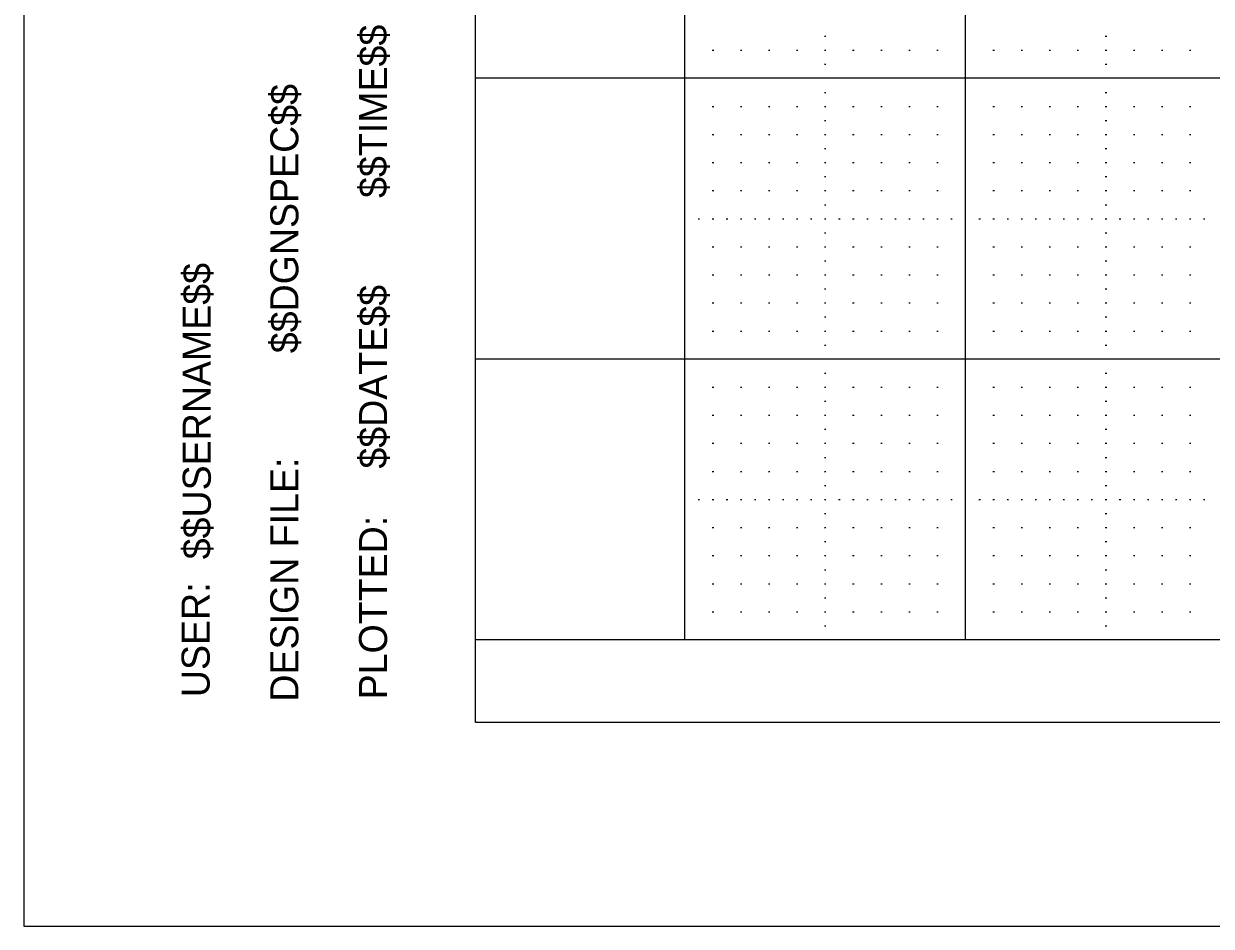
# Model space of a CAD drawing. Extents: x -1.3 to 32.7, y -0.7 to 21.3.
# Drawn here: x -1.263 to 2.967, y -0.727 to 2.487 of the extents above; entities that cross this region are included whole.
import ezdxf

# ---------------------------------------------------------------- set-up
doc = ezdxf.new("R2010")
doc.units = 0
for name, color, linetype in [('Level 1', 7, 'Continuous'), ('Level 4', 7, 'Continuous'), ('Level 5', 7, 'Continuous'), ('Level 63', 7, 'Continuous'), ('R_Border_Dark', 7, 'Continuous')]:
    doc.layers.add(name, color=color, linetype=linetype)

msp = doc.modelspace()

# ---------------------------------------------------------------- linework, layer by layer
at = {"layer": 'Level 1'}
for p, q in [((-1.263, 21.273), (-1.263, -0.727)), ((0.3463, -0.001), (0.3463, 20.545)), ((31.9643, -0.001), (0.3463, -0.001))]:
    msp.add_line(p, q, dxfattribs=at)
at = {"layer": 'Level 4'}
msp.add_line((31.9643, 0.293), (0.3463, 0.293), dxfattribs=at)
at = {"layer": 'Level 5'}
for p, q in [((1.5898, 2.443), (1.5948, 2.443)), ((2.5898, 2.443), (2.5948, 2.443)), ((1.1898, 2.393), (1.1948, 2.393)), ((1.2898, 2.393), (1.2948, 2.393)), ((1.3898, 2.393), (1.3948, 2.393)), ((1.4898, 2.393), (1.4948, 2.393)), ((1.5898, 2.393), (1.5948, 2.393)), ((1.6898, 2.393), (1.6948, 2.393)), ((1.7898, 2.393), (1.7948, 2.393)), ((1.8898, 2.393), (1.8948, 2.393)), ((1.9898, 2.393), (1.9948, 2.393)), ((2.1898, 2.393), (2.1948, 2.393)), ((2.2898, 2.393), (2.2948, 2.393)), ((2.3898, 2.393), (2.3948, 2.393)), ((2.4898, 2.393), (2.4948, 2.393)), ((2.5898, 2.393), (2.5948, 2.393)), ((2.6898, 2.393), (2.6948, 2.393)), ((2.7898, 2.393), (2.7948, 2.393)), ((2.8898, 2.393), (2.8948, 2.393)), ((1.5898, 2.343), (1.5948, 2.343)), ((2.5898, 2.343), (2.5948, 2.343)), ((1.5898, 2.243), (1.5948, 2.243)), ((2.5898, 2.243), (2.5948, 2.243)), ((1.1898, 2.193), (1.1948, 2.193)), ((1.2898, 2.193), (1.2948, 2.193)), ((1.3898, 2.193), (1.3948, 2.193)), ((1.4898, 2.193), (1.4948, 2.193)), ((1.5898, 2.193), (1.5948, 2.193)), ((1.6898, 2.193), (1.6948, 2.193)), ((1.7898, 2.193), (1.7948, 2.193)), ((1.8898, 2.193), (1.8948, 2.193)), ((1.9898, 2.193), (1.9948, 2.193)), ((2.1898, 2.193), (2.1948, 2.193)), ((2.2898, 2.193), (2.2948, 2.193)), ((2.3898, 2.193), (2.3948, 2.193)), ((2.4898, 2.193), (2.4948, 2.193)), ((2.5898, 2.193), (2.5948, 2.193)), ((2.6898, 2.193), (2.6948, 2.193)), ((2.7898, 2.193), (2.7948, 2.193)), ((2.8898, 2.193), (2.8948, 2.193)), ((1.5898, 2.143), (1.5948, 2.143)), ((2.5898, 2.143), (2.5948, 2.143)), ((1.1898, 2.093), (1.1948, 2.093)), ((1.2898, 2.093), (1.2948, 2.093)), ((1.3898, 2.093), (1.3948, 2.093)), ((1.4898, 2.093), (1.4948, 2.093)), ((1.5898, 2.093), (1.5948, 2.093)), ((1.6898, 2.093), (1.6948, 2.093)), ((1.7898, 2.093), (1.7948, 2.093)), ((1.8898, 2.093), (1.8948, 2.093)), ((1.9898, 2.093), (1.9948, 2.093)), ((2.1898, 2.093), (2.1948, 2.093)), ((2.2898, 2.093), (2.2948, 2.093)), ((2.3898, 2.093), (2.3948, 2.093)), ((2.4898, 2.093), (2.4948, 2.093)), ((2.5898, 2.093), (2.5948, 2.093)), ((2.6898, 2.093), (2.6948, 2.093)), ((2.7898, 2.093), (2.7948, 2.093)), ((2.8898, 2.093), (2.8948, 2.093)), ((1.5898, 2.043), (1.5948, 2.043)), ((2.5898, 2.043), (2.5948, 2.043)), ((1.1898, 1.993), (1.1948, 1.993)), ((1.2898, 1.993), (1.2948, 1.993)), ((1.3898, 1.993), (1.3948, 1.993)), ((1.4898, 1.993), (1.4948, 1.993)), ((1.5898, 1.993), (1.5948, 1.993)), ((1.6898, 1.993), (1.6948, 1.993)), ((1.7898, 1.993), (1.7948, 1.993)), ((1.8898, 1.993), (1.8948, 1.993)), ((1.9898, 1.993), (1.9948, 1.993)), ((2.1898, 1.993), (2.1948, 1.993)), ((2.2898, 1.993), (2.2948, 1.993)), ((2.3898, 1.993), (2.3948, 1.993)), ((2.4898, 1.993), (2.4948, 1.993)), ((2.5898, 1.993), (2.5948, 1.993)), ((2.6898, 1.993), (2.6948, 1.993)), ((2.7898, 1.993), (2.7948, 1.993)), ((2.8898, 1.993), (2.8948, 1.993)), ((1.5898, 1.943), (1.5948, 1.943)), ((2.5898, 1.943), (2.5948, 1.943)), ((1.1898, 1.893), (1.1948, 1.893)), ((1.2898, 1.893), (1.2948, 1.893)), ((1.3898, 1.893), (1.3948, 1.893)), ((1.4898, 1.893), (1.4948, 1.893)), ((1.5898, 1.893), (1.5948, 1.893)), ((1.6898, 1.893), (1.6948, 1.893)), ((1.7898, 1.893), (1.7948, 1.893)), ((1.8898, 1.893), (1.8948, 1.893)), ((1.9898, 1.893), (1.9948, 1.893)), ((2.1898, 1.893), (2.1948, 1.893)), ((2.2898, 1.893), (2.2948, 1.893)), ((2.3898, 1.893), (2.3948, 1.893)), ((2.4898, 1.893), (2.4948, 1.893)), ((2.5898, 1.893), (2.5948, 1.893)), ((2.6898, 1.893), (2.6948, 1.893)), ((2.7898, 1.893), (2.7948, 1.893)), ((2.8898, 1.893), (2.8948, 1.893)), ((1.5898, 1.843), (1.5948, 1.843)), ((2.5898, 1.843), (2.5948, 1.843)), ((1.1398, 1.793), (1.1448, 1.793)), ((1.1898, 1.793), (1.1948, 1.793)), ((1.2398, 1.793), (1.2448, 1.793)), ((1.2898, 1.793), (1.2948, 1.793)), ((1.3398, 1.793), (1.3448, 1.793)), ((1.3898, 1.793), (1.3948, 1.793)), ((1.4398, 1.793), (1.4448, 1.793)), ((1.4898, 1.793), (1.4948, 1.793)), ((1.5398, 1.793), (1.5448, 1.793)), ((1.5898, 1.793), (1.5948, 1.793)), ((1.6398, 1.793), (1.6448, 1.793)), ((1.6898, 1.793), (1.6948, 1.793)), ((1.7398, 1.793), (1.7448, 1.793)), ((1.7898, 1.793), (1.7948, 1.793)), ((1.8398, 1.793), (1.8448, 1.793)), ((1.8898, 1.793), (1.8948, 1.793)), ((1.9398, 1.793), (1.9448, 1.793)), ((1.9898, 1.793), (1.9948, 1.793)), ((2.0398, 1.793), (2.0448, 1.793)), ((2.1398, 1.793), (2.1448, 1.793)), ((2.1898, 1.793), (2.1948, 1.793)), ((2.2398, 1.793), (2.2448, 1.793)), ((2.2898, 1.793), (2.2948, 1.793)), ((2.3398, 1.793), (2.3448, 1.793)), ((2.3898, 1.793), (2.3948, 1.793)), ((2.4398, 1.793), (2.4448, 1.793)), ((2.4898, 1.793), (2.4948, 1.793)), ((2.5398, 1.793), (2.5448, 1.793)), ((2.5898, 1.793), (2.5948, 1.793)), ((2.6398, 1.793), (2.6448, 1.793)), ((2.6898, 1.793), (2.6948, 1.793)), ((2.7398, 1.793), (2.7448, 1.793)), ((2.7898, 1.793), (2.7948, 1.793)), ((2.8398, 1.793), (2.8448, 1.793)), ((2.8898, 1.793), (2.8948, 1.793)), ((2.9398, 1.793), (2.9448, 1.793)), ((1.5898, 1.743), (1.5948, 1.743)), ((2.5898, 1.743), (2.5948, 1.743)), ((1.1898, 1.693), (1.1948, 1.693)), ((1.2898, 1.693), (1.2948, 1.693)), ((1.3898, 1.693), (1.3948, 1.693)), ((1.4898, 1.693), (1.4948, 1.693)), ((1.5898, 1.693), (1.5948, 1.693)), ((1.6898, 1.693), (1.6948, 1.693)), ((1.7898, 1.693), (1.7948, 1.693)), ((1.8898, 1.693), (1.8948, 1.693)), ((1.9898, 1.693), (1.9948, 1.693)), ((2.1898, 1.693), (2.1948, 1.693)), ((2.2898, 1.693), (2.2948, 1.693)), ((2.3898, 1.693), (2.3948, 1.693)), ((2.4898, 1.693), (2.4948, 1.693)), ((2.5898, 1.693), (2.5948, 1.693)), ((2.6898, 1.693), (2.6948, 1.693)), ((2.7898, 1.693), (2.7948, 1.693)), ((2.8898, 1.693), (2.8948, 1.693)), ((1.5898, 1.643), (1.5948, 1.643)), ((2.5898, 1.643), (2.5948, 1.643)), ((1.1898, 1.593), (1.1948, 1.593)), ((1.2898, 1.593), (1.2948, 1.593)), ((1.3898, 1.593), (1.3948, 1.593)), ((1.4898, 1.593), (1.4948, 1.593)), ((1.5898, 1.593), (1.5948, 1.593)), ((1.6898, 1.593), (1.6948, 1.593)), ((1.7898, 1.593), (1.7948, 1.593)), ((1.8898, 1.593), (1.8948, 1.593)), ((1.9898, 1.593), (1.9948, 1.593)), ((2.1898, 1.593), (2.1948, 1.593)), ((2.2898, 1.593), (2.2948, 1.593)), ((2.3898, 1.593), (2.3948, 1.593)), ((2.4898, 1.593), (2.4948, 1.593)), ((2.5898, 1.593), (2.5948, 1.593)), ((2.6898, 1.593), (2.6948, 1.593)), ((2.7898, 1.593), (2.7948, 1.593)), ((2.8898, 1.593), (2.8948, 1.593)), ((1.5898, 1.543), (1.5948, 1.543)), ((2.5898, 1.543), (2.5948, 1.543)), ((1.1898, 1.493), (1.1948, 1.493)), ((1.2898, 1.493), (1.2948, 1.493)), ((1.3898, 1.493), (1.3948, 1.493)), ((1.4898, 1.493), (1.4948, 1.493)), ((1.5898, 1.493), (1.5948, 1.493)), ((1.6898, 1.493), (1.6948, 1.493)), ((1.7898, 1.493), (1.7948, 1.493)), ((1.8898, 1.493), (1.8948, 1.493)), ((1.9898, 1.493), (1.9948, 1.493)), ((2.1898, 1.493), (2.1948, 1.493)), ((2.2898, 1.493), (2.2948, 1.493)), ((2.3898, 1.493), (2.3948, 1.493)), ((2.4898, 1.493), (2.4948, 1.493)), ((2.5898, 1.493), (2.5948, 1.493)), ((2.6898, 1.493), (2.6948, 1.493)), ((2.7898, 1.493), (2.7948, 1.493)), ((2.8898, 1.493), (2.8948, 1.493)), ((1.5898, 1.443), (1.5948, 1.443)), ((2.5898, 1.443), (2.5948, 1.443)), ((1.1898, 1.393), (1.1948, 1.393)), ((1.2898, 1.393), (1.2948, 1.393)), ((1.3898, 1.393), (1.3948, 1.393)), ((1.4898, 1.393), (1.4948, 1.393)), ((1.5898, 1.393), (1.5948, 1.393)), ((1.6898, 1.393), (1.6948, 1.393)), ((1.7898, 1.393), (1.7948, 1.393)), ((1.8898, 1.393), (1.8948, 1.393)), ((1.9898, 1.393), (1.9948, 1.393)), ((2.1898, 1.393), (2.1948, 1.393)), ((2.2898, 1.393), (2.2948, 1.393)), ((2.3898, 1.393), (2.3948, 1.393)), ((2.4898, 1.393), (2.4948, 1.393)), ((2.5898, 1.393), (2.5948, 1.393)), ((2.6898, 1.393), (2.6948, 1.393)), ((2.7898, 1.393), (2.7948, 1.393)), ((2.8898, 1.393), (2.8948, 1.393)), ((1.5898, 1.343), (1.5948, 1.343)), ((2.5898, 1.343), (2.5948, 1.343)), ((1.5898, 1.243), (1.5948, 1.243)), ((2.5898, 1.243), (2.5948, 1.243)), ((1.1898, 1.193), (1.1948, 1.193)), ((1.2898, 1.193), (1.2948, 1.193)), ((1.3898, 1.193), (1.3948, 1.193)), ((1.4898, 1.193), (1.4948, 1.193)), ((1.5898, 1.193), (1.5948, 1.193)), ((1.6898, 1.193), (1.6948, 1.193)), ((1.7898, 1.193), (1.7948, 1.193)), ((1.8898, 1.193), (1.8948, 1.193)), ((1.9898, 1.193), (1.9948, 1.193)), ((2.1898, 1.193), (2.1948, 1.193)), ((2.2898, 1.193), (2.2948, 1.193)), ((2.3898, 1.193), (2.3948, 1.193)), ((2.4898, 1.193), (2.4948, 1.193)), ((2.5898, 1.193), (2.5948, 1.193)), ((2.6898, 1.193), (2.6948, 1.193)), ((2.7898, 1.193), (2.7948, 1.193)), ((2.8898, 1.193), (2.8948, 1.193)), ((1.5898, 1.143), (1.5948, 1.143)), ((2.5898, 1.143), (2.5948, 1.143)), ((1.1898, 1.093), (1.1948, 1.093)), ((1.2898, 1.093), (1.2948, 1.093)), ((1.3898, 1.093), (1.3948, 1.093)), ((1.4898, 1.093), (1.4948, 1.093)), ((1.5898, 1.093), (1.5948, 1.093)), ((1.6898, 1.093), (1.6948, 1.093)), ((1.7898, 1.093), (1.7948, 1.093)), ((1.8898, 1.093), (1.8948, 1.093)), ((1.9898, 1.093), (1.9948, 1.093)), ((2.1898, 1.093), (2.1948, 1.093)), ((2.2898, 1.093), (2.2948, 1.093)), ((2.3898, 1.093), (2.3948, 1.093)), ((2.4898, 1.093), (2.4948, 1.093)), ((2.5898, 1.093), (2.5948, 1.093)), ((2.6898, 1.093), (2.6948, 1.093)), ((2.7898, 1.093), (2.7948, 1.093)), ((2.8898, 1.093), (2.8948, 1.093)), ((1.5898, 1.043), (1.5948, 1.043)), ((2.5898, 1.043), (2.5948, 1.043)), ((1.1898, 0.993), (1.1948, 0.993)), ((1.2898, 0.993), (1.2948, 0.993)), ((1.3898, 0.993), (1.3948, 0.993)), ((1.4898, 0.993), (1.4948, 0.993)), ((1.5898, 0.993), (1.5948, 0.993)), ((1.6898, 0.993), (1.6948, 0.993)), ((1.7898, 0.993), (1.7948, 0.993)), ((1.8898, 0.993), (1.8948, 0.993)), ((1.9898, 0.993), (1.9948, 0.993)), ((2.1898, 0.993), (2.1948, 0.993)), ((2.2898, 0.993), (2.2948, 0.993)), ((2.3898, 0.993), (2.3948, 0.993)), ((2.4898, 0.993), (2.4948, 0.993)), ((2.5898, 0.993), (2.5948, 0.993)), ((2.6898, 0.993), (2.6948, 0.993)), ((2.7898, 0.993), (2.7948, 0.993)), ((2.8898, 0.993), (2.8948, 0.993)), ((1.5898, 0.943), (1.5948, 0.943)), ((2.5898, 0.943), (2.5948, 0.943)), ((1.1898, 0.893), (1.1948, 0.893)), ((1.2898, 0.893), (1.2948, 0.893)), ((1.3898, 0.893), (1.3948, 0.893)), ((1.4898, 0.893), (1.4948, 0.893)), ((1.5898, 0.893), (1.5948, 0.893)), ((1.6898, 0.893), (1.6948, 0.893)), ((1.7898, 0.893), (1.7948, 0.893)), ((1.8898, 0.893), (1.8948, 0.893)), ((1.9898, 0.893), (1.9948, 0.893)), ((2.1898, 0.893), (2.1948, 0.893)), ((2.2898, 0.893), (2.2948, 0.893)), ((2.3898, 0.893), (2.3948, 0.893)), ((2.4898, 0.893), (2.4948, 0.893)), ((2.5898, 0.893), (2.5948, 0.893)), ((2.6898, 0.893), (2.6948, 0.893)), ((2.7898, 0.893), (2.7948, 0.893)), ((2.8898, 0.893), (2.8948, 0.893)), ((1.5898, 0.843), (1.5948, 0.843)), ((2.5898, 0.843), (2.5948, 0.843)), ((1.1398, 0.793), (1.1448, 0.793)), ((1.1898, 0.793), (1.1948, 0.793)), ((1.2398, 0.793), (1.2448, 0.793)), ((1.2898, 0.793), (1.2948, 0.793)), ((1.3398, 0.793), (1.3448, 0.793)), ((1.3898, 0.793), (1.3948, 0.793)), ((1.4398, 0.793), (1.4448, 0.793)), ((1.4898, 0.793), (1.4948, 0.793)), ((1.5398, 0.793), (1.5448, 0.793)), ((1.5898, 0.793), (1.5948, 0.793)), ((1.6398, 0.793), (1.6448, 0.793)), ((1.6898, 0.793), (1.6948, 0.793)), ((1.7398, 0.793), (1.7448, 0.793)), ((1.7898, 0.793), (1.7948, 0.793)), ((1.8398, 0.793), (1.8448, 0.793)), ((1.8898, 0.793), (1.8948, 0.793)), ((1.9398, 0.793), (1.9448, 0.793)), ((1.9898, 0.793), (1.9948, 0.793)), ((2.0398, 0.793), (2.0448, 0.793)), ((2.1398, 0.793), (2.1448, 0.793)), ((2.1898, 0.793), (2.1948, 0.793)), ((2.2398, 0.793), (2.2448, 0.793)), ((2.2898, 0.793), (2.2948, 0.793)), ((2.3398, 0.793), (2.3448, 0.793)), ((2.3898, 0.793), (2.3948, 0.793)), ((2.4398, 0.793), (2.4448, 0.793)), ((2.4898, 0.793), (2.4948, 0.793)), ((2.5398, 0.793), (2.5448, 0.793)), ((2.5898, 0.793), (2.5948, 0.793)), ((2.6398, 0.793), (2.6448, 0.793)), ((2.6898, 0.793), (2.6948, 0.793)), ((2.7398, 0.793), (2.7448, 0.793)), ((2.7898, 0.793), (2.7948, 0.793)), ((2.8398, 0.793), (2.8448, 0.793)), ((2.8898, 0.793), (2.8948, 0.793)), ((2.9398, 0.793), (2.9448, 0.793)), ((1.5898, 0.743), (1.5948, 0.743)), ((2.5898, 0.743), (2.5948, 0.743)), ((1.1898, 0.693), (1.1948, 0.693)), ((1.2898, 0.693), (1.2948, 0.693)), ((1.3898, 0.693), (1.3948, 0.693)), ((1.4898, 0.693), (1.4948, 0.693)), ((1.5898, 0.693), (1.5948, 0.693)), ((1.6898, 0.693), (1.6948, 0.693)), ((1.7898, 0.693), (1.7948, 0.693)), ((1.8898, 0.693), (1.8948, 0.693)), ((1.9898, 0.693), (1.9948, 0.693)), ((2.1898, 0.693), (2.1948, 0.693)), ((2.2898, 0.693), (2.2948, 0.693)), ((2.3898, 0.693), (2.3948, 0.693)), ((2.4898, 0.693), (2.4948, 0.693)), ((2.5898, 0.693), (2.5948, 0.693)), ((2.6898, 0.693), (2.6948, 0.693)), ((2.7898, 0.693), (2.7948, 0.693)), ((2.8898, 0.693), (2.8948, 0.693)), ((1.5898, 0.643), (1.5948, 0.643)), ((2.5898, 0.643), (2.5948, 0.643)), ((1.1898, 0.593), (1.1948, 0.593)), ((1.2898, 0.593), (1.2948, 0.593)), ((1.3898, 0.593), (1.3948, 0.593)), ((1.4898, 0.593), (1.4948, 0.593)), ((1.5898, 0.593), (1.5948, 0.593)), ((1.6898, 0.593), (1.6948, 0.593)), ((1.7898, 0.593), (1.7948, 0.593)), ((1.8898, 0.593), (1.8948, 0.593)), ((1.9898, 0.593), (1.9948, 0.593)), ((2.1898, 0.593), (2.1948, 0.593)), ((2.2898, 0.593), (2.2948, 0.593)), ((2.3898, 0.593), (2.3948, 0.593)), ((2.4898, 0.593), (2.4948, 0.593)), ((2.5898, 0.593), (2.5948, 0.593)), ((2.6898, 0.593), (2.6948, 0.593)), ((2.7898, 0.593), (2.7948, 0.593)), ((2.8898, 0.593), (2.8948, 0.593)), ((1.5898, 0.543), (1.5948, 0.543)), ((2.5898, 0.543), (2.5948, 0.543)), ((1.1898, 0.493), (1.1948, 0.493)), ((1.2898, 0.493), (1.2948, 0.493)), ((1.3898, 0.493), (1.3948, 0.493)), ((1.4898, 0.493), (1.4948, 0.493)), ((1.5898, 0.493), (1.5948, 0.493)), ((1.6898, 0.493), (1.6948, 0.493)), ((1.7898, 0.493), (1.7948, 0.493)), ((1.8898, 0.493), (1.8948, 0.493)), ((1.9898, 0.493), (1.9948, 0.493)), ((2.1898, 0.493), (2.1948, 0.493)), ((2.2898, 0.493), (2.2948, 0.493)), ((2.3898, 0.493), (2.3948, 0.493)), ((2.4898, 0.493), (2.4948, 0.493)), ((2.5898, 0.493), (2.5948, 0.493)), ((2.6898, 0.493), (2.6948, 0.493)), ((2.7898, 0.493), (2.7948, 0.493)), ((2.8898, 0.493), (2.8948, 0.493)), ((1.5898, 0.443), (1.5948, 0.443)), ((2.5898, 0.443), (2.5948, 0.443)), ((1.1898, 0.393), (1.1948, 0.393)), ((1.2898, 0.393), (1.2948, 0.393)), ((1.3898, 0.393), (1.3948, 0.393)), ((1.4898, 0.393), (1.4948, 0.393)), ((1.5898, 0.393), (1.5948, 0.393)), ((1.6898, 0.393), (1.6948, 0.393)), ((1.7898, 0.393), (1.7948, 0.393)), ((1.8898, 0.393), (1.8948, 0.393)), ((1.9898, 0.393), (1.9948, 0.393)), ((2.1898, 0.393), (2.1948, 0.393)), ((2.2898, 0.393), (2.2948, 0.393)), ((2.3898, 0.393), (2.3948, 0.393)), ((2.4898, 0.393), (2.4948, 0.393)), ((2.5898, 0.393), (2.5948, 0.393)), ((2.6898, 0.393), (2.6948, 0.393)), ((2.7898, 0.393), (2.7948, 0.393)), ((2.8898, 0.393), (2.8948, 0.393)), ((1.5898, 0.343), (1.5948, 0.343)), ((2.5898, 0.343), (2.5948, 0.343))]:
    msp.add_line(p, q, dxfattribs=at)
at = {"layer": 'Level 63'}
msp.add_lwpolyline([(-1.263, -0.727), (32.737, -0.727), (32.737, 21.273), (-1.263, 21.273)], close=True, dxfattribs=at)
msp.add_lwpolyline([(31.0923, 10.293), (31.0923, 0.293), (1.0923, 0.293), (1.0923, 8.293)], dxfattribs=at)
at = {"layer": 'R_Border_Dark'}
for p, q in [((1.0923, 0.293), (1.0923, 10.293)), ((2.0923, 0.293), (2.0923, 10.293)), ((31.9643, 2.293), (0.3463, 2.293)), ((31.9643, 1.293), (0.3463, 1.293))]:
    msp.add_line(p, q, dxfattribs=at)
msp.add_lwpolyline([(31.0923, 10.293), (31.0923, 0.293), (1.0923, 0.293), (1.0923, 8.293)], dxfattribs=at)

# ---------------------------------------------------------------- texts
at = {"layer": 'Level 1'}
for s, height, p in [('$$TIME$$', 0.1, (0.0313, 1.867)), ('$$DGNSPEC$$', 0.100002, (-0.2847, 1.314)), ('$$USERNAME$$', 0.100002, (-0.5967, 0.58)), ('$$DATE$$', 0.1, (0.0313, 0.903)), ('DESIGN FILE:', 0.100002, (-0.2847, 0.073)), ('PLOTTED:', 0.1, (0.0313, 0.081)), ('USER:', 0.1, (-0.6007, 0.089))]:
    msp.add_text(s, height=height, rotation=90, dxfattribs=at).set_placement(p)

doc.saveas('drawing.dxf')
